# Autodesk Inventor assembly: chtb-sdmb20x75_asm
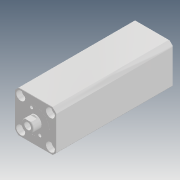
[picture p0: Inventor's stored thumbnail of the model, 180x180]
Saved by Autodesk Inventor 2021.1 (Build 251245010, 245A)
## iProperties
Company: Microsoft
Created: 2018-05
Part Number: chtb-sdmb20x75_asm
Description: STEP AP214
Document SubType Name: Assembly
Designer: user
Title: chtb-sdmb20x75_asm.STEP
Author: Windows
Revision Number: ÈÎºÎ
Sending System: SolidWorks 2015
Preprocessor: SwSTEP 2.0
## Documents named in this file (4)
- D:\Vault_2016\Projekty\Clamptek\Hydraulic\CHTB\CHTB-20\Inventor\CHTB-SDMB20x75\chtb-sdmb20x75_asm.iam
- D:\Vault_2016\Projekty\Clamptek\Hydraulic\CHTB\CHTB-20\Inventor\CHTB-SDMB20x75\CHTB-SDMB20X75NBT.ipt
- D:\Vault_2016\Projekty\Clamptek\Hydraulic\CHTB\CHTB-20\Inventor\CHTB-SDMB20x75\CHTB-SDMB20X75NHSG.ipt
- D:\Vault_2016\Projekty\Clamptek\Hydraulic\CHTB\CHTB-20\Inventor\CHTB-SDMB20x75\QG_3.ipt
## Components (3 placed, 3 different names)
1. CHTB-SDMB20X75NBT_1
2. CHTB-SDMB20X75NHSG_2
3. QG_3_3
